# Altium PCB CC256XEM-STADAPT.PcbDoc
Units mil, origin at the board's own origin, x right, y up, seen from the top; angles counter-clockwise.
Board outline 2600 x 2900 mil, 4 copper layers (Top Layer, Layer 2, Layer 3, Bottom Layer), stack 62 mil thick; 64 components, 60 nets, 306 pads, 134 vias.
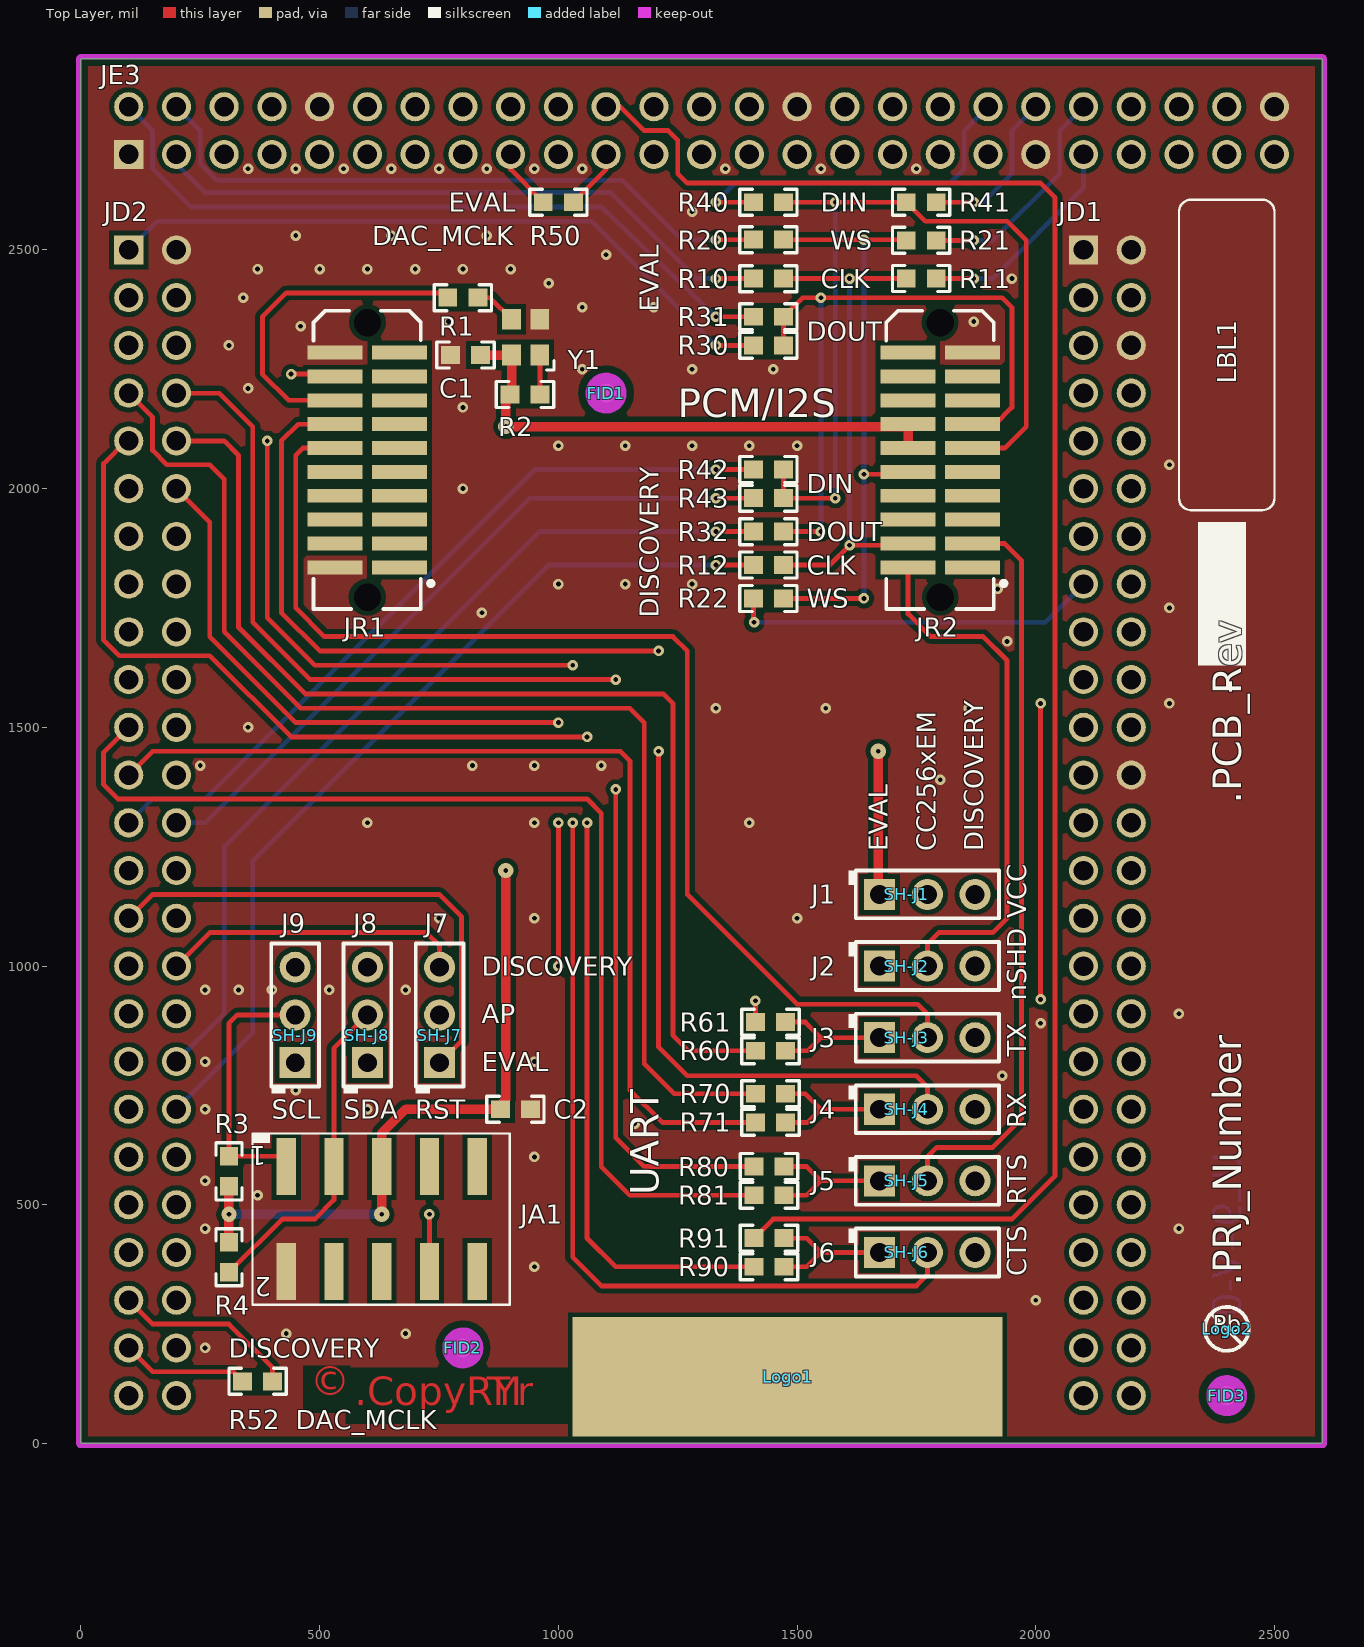
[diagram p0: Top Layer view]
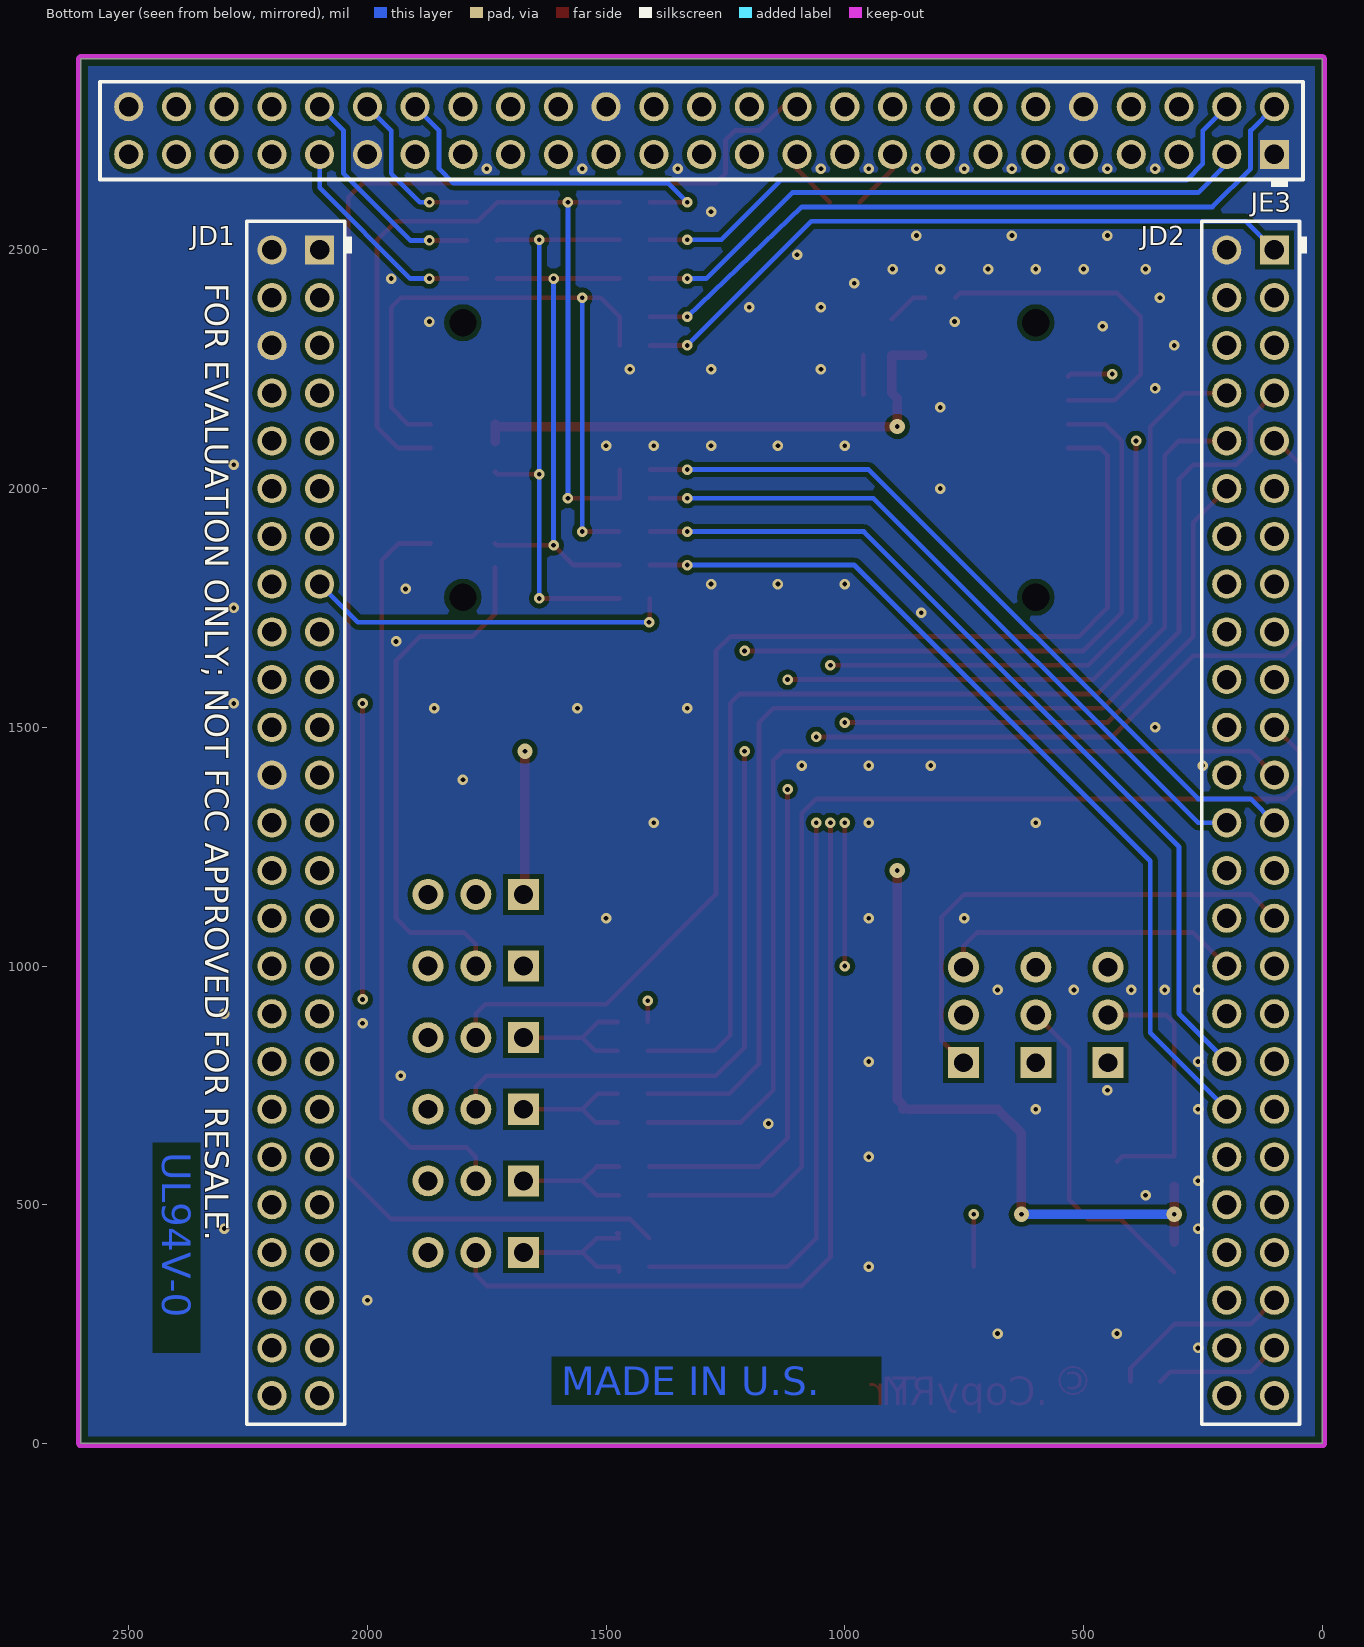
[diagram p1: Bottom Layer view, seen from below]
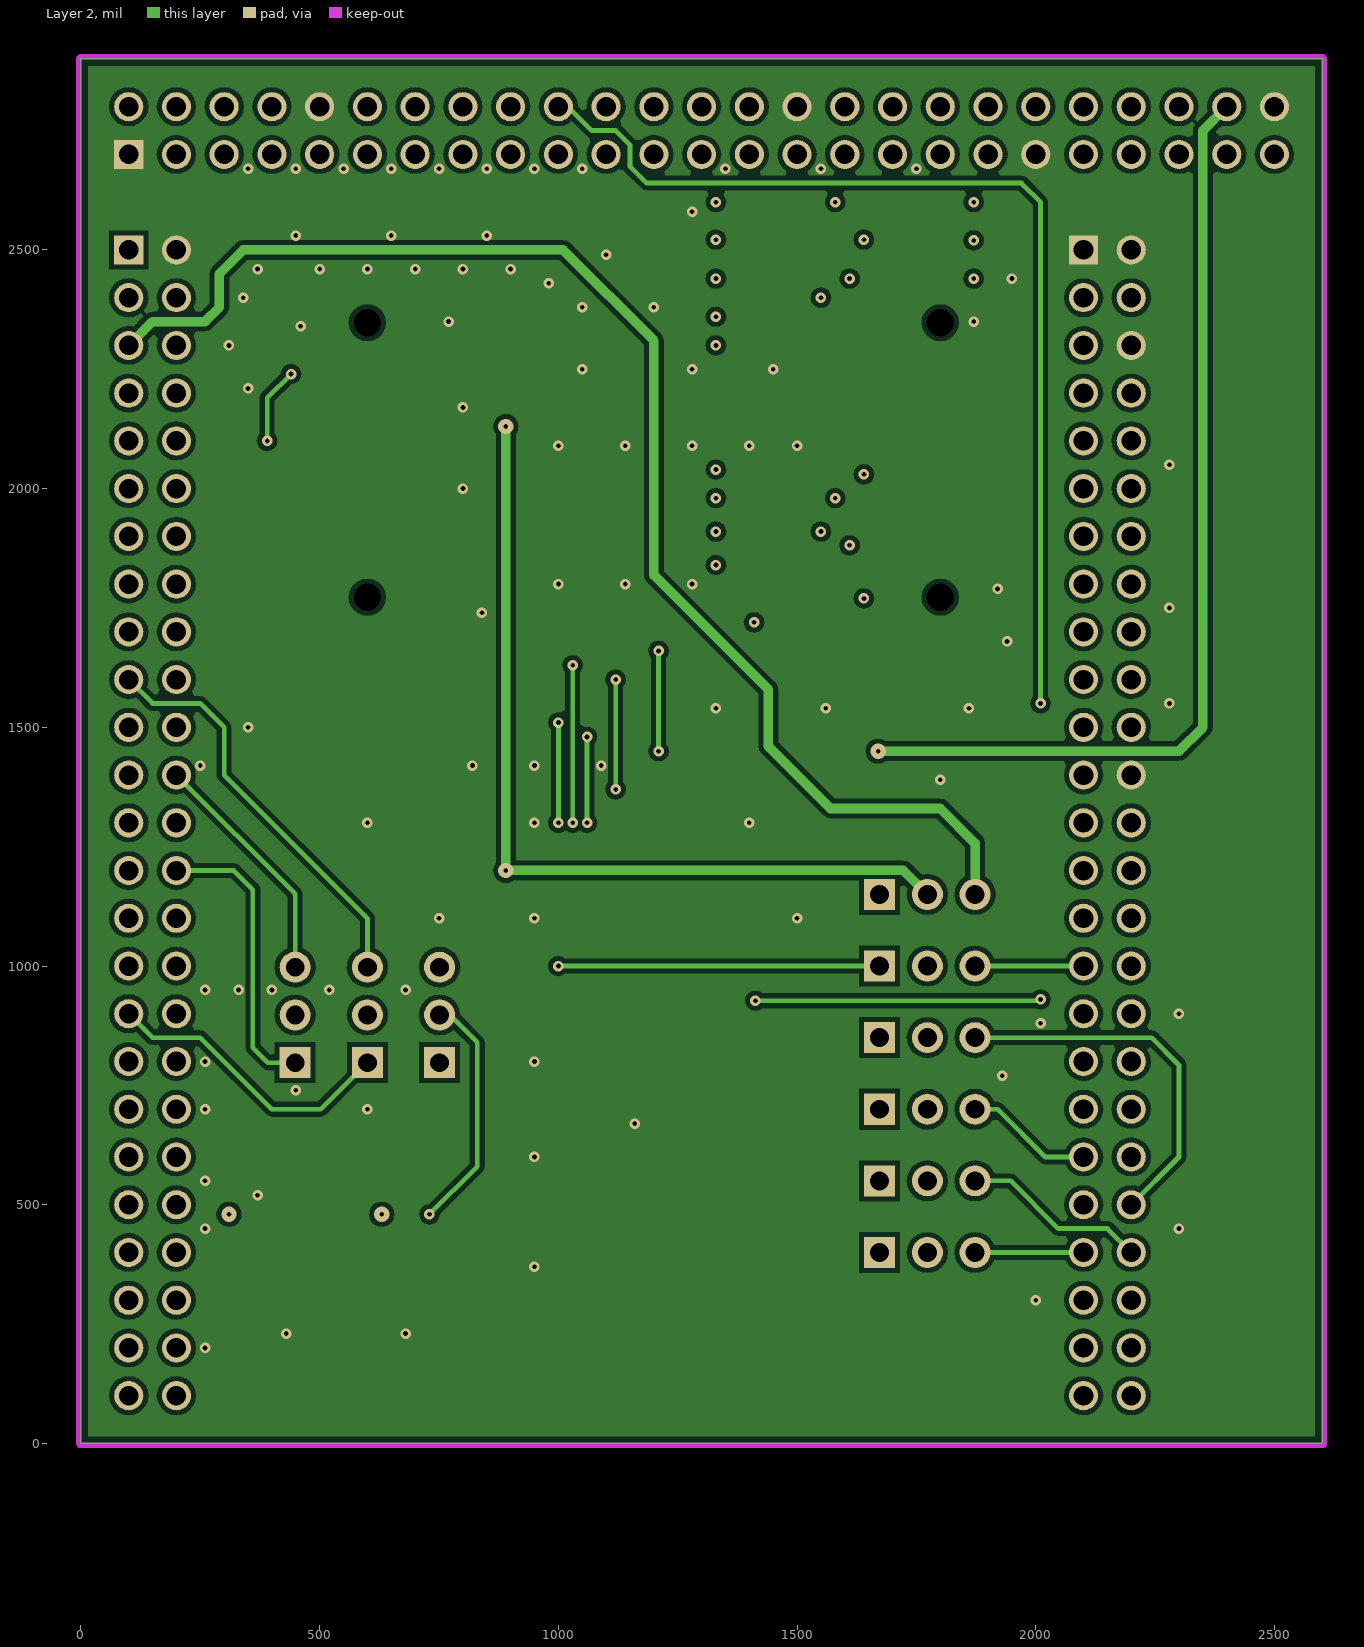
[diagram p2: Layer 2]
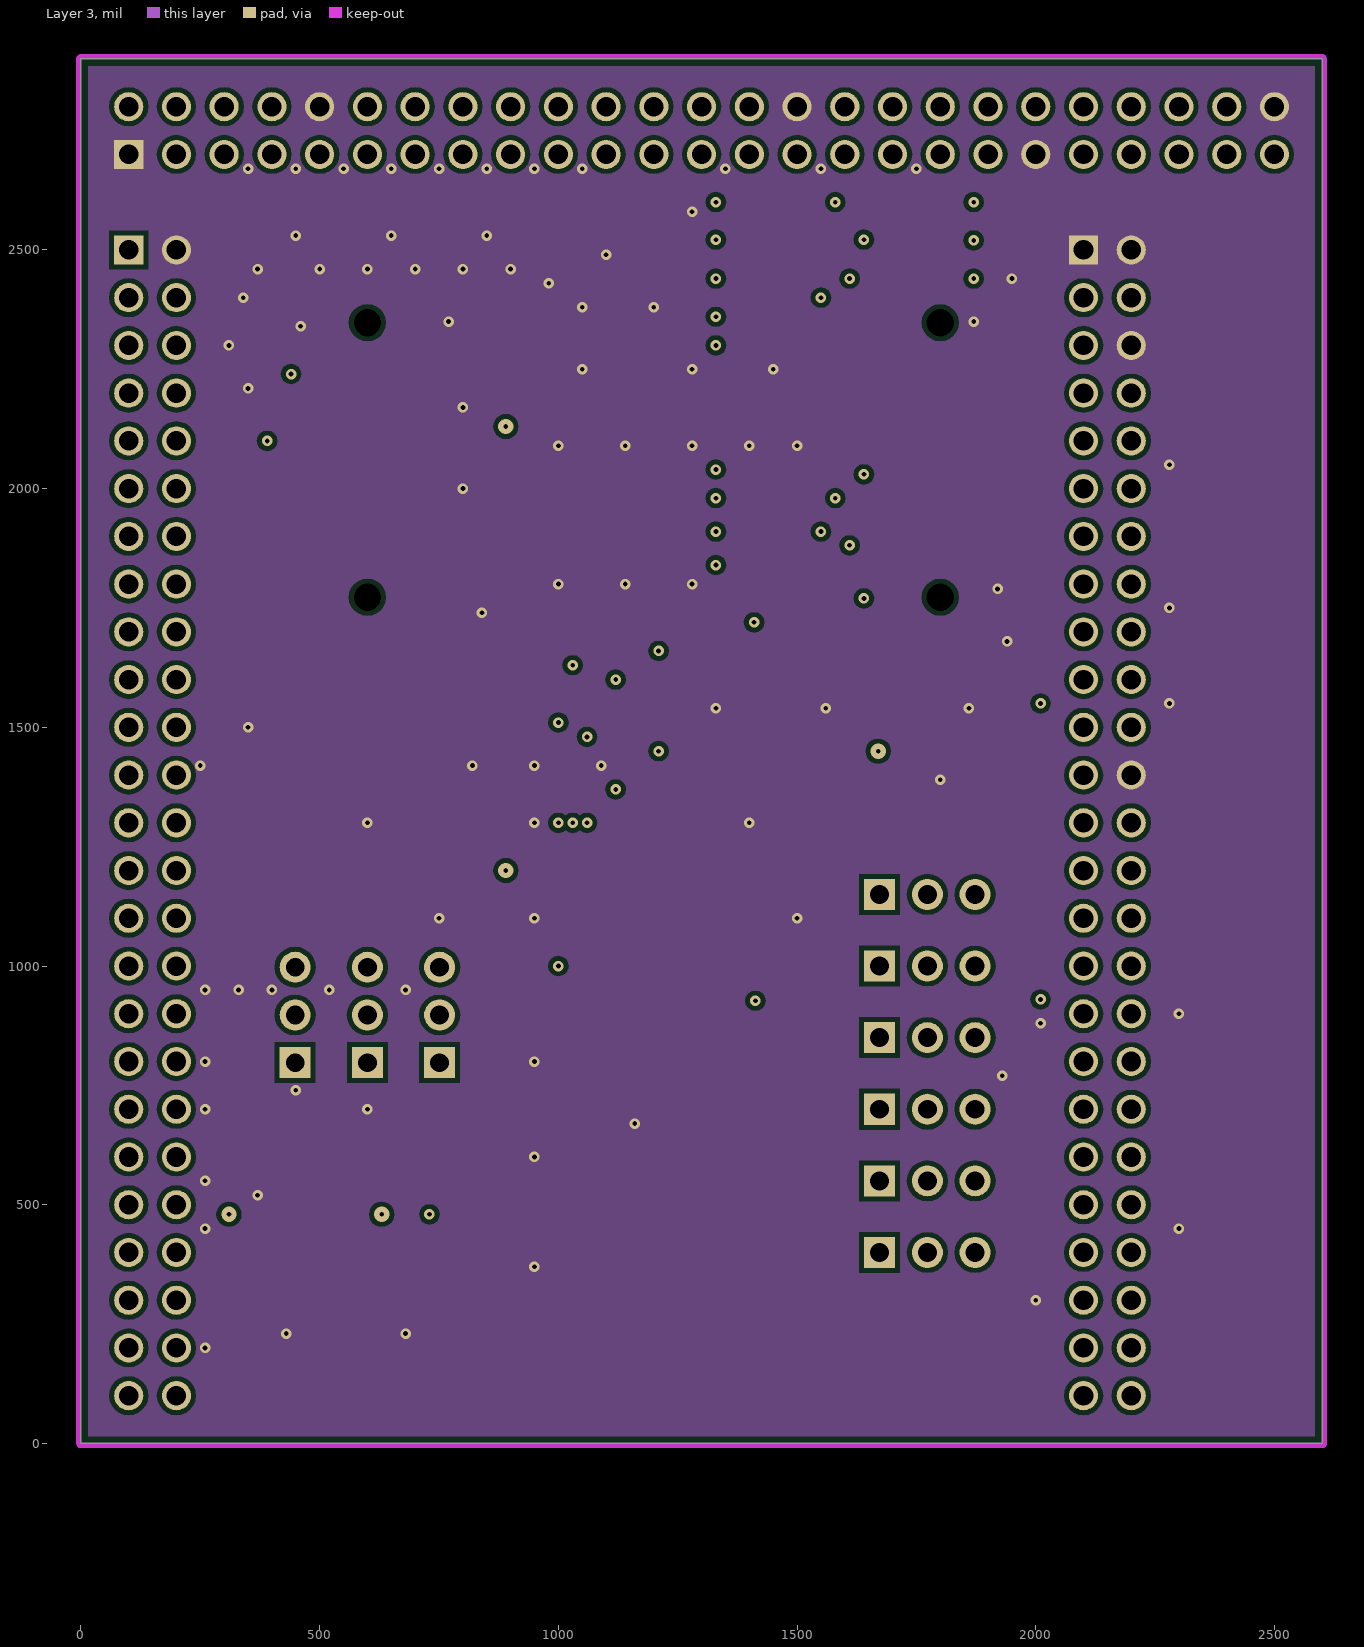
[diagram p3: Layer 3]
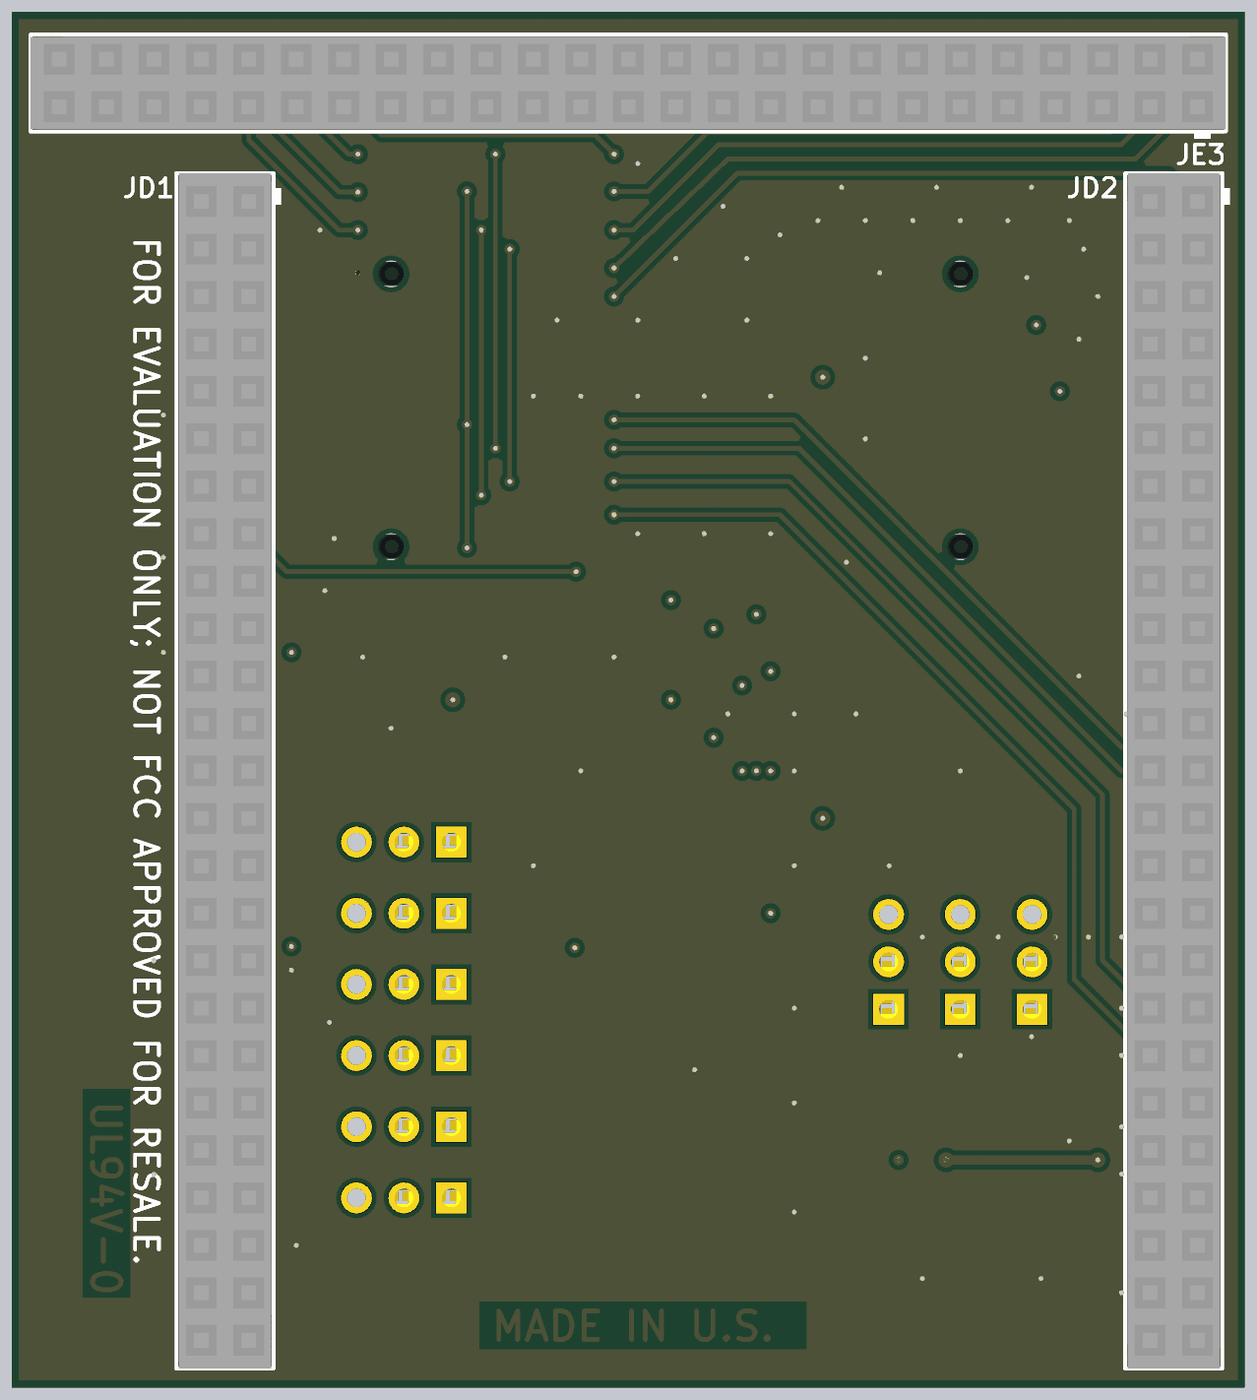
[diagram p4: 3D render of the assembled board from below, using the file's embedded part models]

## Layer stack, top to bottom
Top Solder: solder mask 0.4, Solder Resist, Dk 3.5
Top Layer: signal copper 1.4
Dielectric 1: core 10, FR-4, Dk 4.8
Layer 2: signal copper 1.4
Dielectric 2: prepreg 36.4, FR-4, Dk 4.8
Layer 3: signal copper 1.4
Dielectric 3: core 10, FR-4, Dk 4.8
Bottom Layer: signal copper 1.4
Bottom Solder: solder mask 0.4, Solder Resist, Dk 3.5

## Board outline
0,0 2600,0 2600,2900 0,2900

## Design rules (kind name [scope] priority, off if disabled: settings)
AcuteAngle [All] p1: minimum=4.50000000000000E+0001 checktracksonly=FALSE
AssemblyTestPointUsage [All] p1: valid=2
Clearance Clearance_Keepouts [((IsTrack Or IsArc) And Not InPoly) And IsFree and IsKeepOut vs ((IsTrack Or IsArc) And Not InPoly) And IsFree and IsKeepOut] p1: gap=0
Clearance Clearance_BoardEdge_MountingHoles [OnCopper and InComponentClass('Mounting Holes') vs IsKeepOut] p2: gap=40
Clearance Clearance_BoardEdge_Poly [OnCopper and InPoly vs IsKeepOut] p3: gap=15
Clearance Clearance_BoardEdge [OnCopper and Not InComponentClass('Logo') and not InComponentClass('FiducialMark') and not InRegion(1000,500,4000,800) and Not IsKeepout vs IsKeepOut] p4: gap=15
Clearance Clearance_Poly [InPolygon] p5: gap=10
Clearance [All] p6: gap=8
ComponentClearance ComponentClearance_MountingHoles_FiducialMarks [InComponentClass('Mounting Holes') vs InComponentClass('FiducialMark')] p1: gap=50 collisioncheckmode=3 verticalgap=10 showdistances=FALSE
ComponentClearance ComponentClearance_Shunt [InComponentClass('Header') vs InComponentClass('Shunt')] p2: gap=0 collisioncheckmode=3 verticalgap=0 showdistances=FALSE
ComponentClearance ComponentClearance_Logo [InComponentClass('Logo')] p3: gap=50 collisioncheckmode=3 verticalgap=10 showdistances=FALSE
ComponentClearance ComponentClearance_ScrewToNut [(HasFootprint('NY PMS 440 0025 PH')) vs (HasFootprint('Keystone_1902C'))] p4: gap=5 collisioncheckmode=3 verticalgap=10 showdistances=FALSE
ComponentClearance ComponentClearance_MountingHoles [InComponentClass('Mounting Holes')] p5: gap=250 collisioncheckmode=3 verticalgap=100000 showdistances=FALSE
ComponentClearance ComponentClearance_SmallPassives [HasFootprint('0201*') or HasFootprint('0402*') or HasFootprint('0508') or HasFootprint('0603*') or HasFootprint('0612') or HasFootprint('0805*') or HasFootprint('0815*') or HasFootprint('0830*') or HasFootprint('1206*') or HasFootprint('1210*') or HasFootprint('1808*') or HasFootprint('1812*') or HasFootprint('1825*') or HasFootprint('2010*') or HasFootprint('2220*') or HasFootprint('2225*') or HasFootprint('2512*') or HasFootprint('2728*') or HasFootprint('3518*') vs HasFootprint('0201*') or HasFootprint('0402*') or HasFootprint('0508') or HasFootprint('0603*') or HasFootprint('0612') or HasFootprint('0805*') or HasFootprint('0815*') or HasFootprint('0830*') or HasFootprint('1206*') or HasFootprint('1210*') or HasFootprint('1808*') or HasFootprint('1812*') or HasFootprint('1825*') or HasFootprint('2010*') or HasFootprint('2220*') or HasFootprint('2225*') or HasFootprint('2512*') or HasFootprint('2728*') or HasFootprint('3518*')] p6: gap=20 collisioncheckmode=3 verticalgap=10 showdistances=FALSE
ComponentClearance ComponentClearance_THtoSMT [IsThruComponent vs IsSMTComponent] p7: gap=40 collisioncheckmode=3 verticalgap=30 showdistances=FALSE
ComponentClearance ComponentClearance_THtoTH [IsThruComponent vs IsThruComponent] p8: gap=40 collisioncheckmode=3 verticalgap=30 showdistances=FALSE
ComponentClearance [All] p9: gap=40 collisioncheckmode=3 verticalgap=10 showdistances=FALSE
DiffPairsRouting [All] p1: maxlimit=100 minlimit=10 mostfreqgap=10 toplayer_minwidth=15 toplayer_maxwidth=15 toplayer_prefwidth=15 midlayer1_minwidth=15 midlayer1_maxwidth=15 midlayer1_prefwidth=15 midlayer2_minwidth=15 midlayer2_maxwidth=15 midlayer2_prefwidth=15 bottomlayer_minwidth=15 bottomlayer_maxwidth=15 bottomlayer_prefwidth=15 maxuncoupledlength=1000
FabricationTestPointUsage TestPointUsage [All] p1: valid=2 allowmultiple=FALSE
FabricationTestpoint Testpoint [All] p1: side=3 testpointundercomponent=TRUE minsize=40 maxsize=100 preferedsize=60 minholesize=0 maxholesize=40 preferedholesize=32 testpointgrid=1 allowsidetop=TRUE allowsidebottom=TRUE usegrid=TRUE gridtolerance=0.01
FanoutControl Fanout_LCC [IsLCC] p1: bgadir=Out bgaviamode=Centered fanoutstyle=Auto fanoutdirection=Alternating viagrid=1 // Fanout_LCC (Default Rule)
FanoutControl Fanout_BGA [IsBGA] p2: bgadir=Out bgaviamode=Centered fanoutstyle=Auto fanoutdirection=Alternating viagrid=1 // Fanout_BGA (Default Rule)
FanoutControl Fanout_Default [All] p4: bgadir=Out bgaviamode=Centered fanoutstyle=Auto fanoutdirection=Alternating viagrid=1 // Fanout_Default (Default Rule)
FanoutControl Fanout_Small [(CompPinCount < 5)] p5: bgadir=Out bgaviamode=Centered fanoutstyle=Auto fanoutdirection=OutThenIn viagrid=1 // Fanout_Small (Default Rule)
HoleSize [All] p1: absolutevalues=TRUE maxlimit=251 minlimit=10 maxpercent=80.000 minpercent=20.000
MinimumAnnularRing MinimumAnnularRing_ThermalPadVias [IsVia and InAnyComponent] p1: minimumring=6
MinimumAnnularRing [All] p2: minimumring=5
MinimumSolderMaskSliver MinimumSolderMaskSliver_Logo [InComponentClass('Logo') vs InComponentClass('Logo')] p1: minsoldermaskwidth=0.7
MinimumSolderMaskSliver [All] p2: minsoldermaskwidth=3.94
PlaneConnect [All] p1: planeconnectstyle=Relief reliefexpansion=10 reliefentries=4 reliefconductorwidth=10 reliefairgap=10
PolygonConnect [All] p1: connectstyle=Direct reliefconductorwidth=10 reliefentries=4 polygonreliefangle="90 Angle" airgapwidth=10
RoutingVias ThermalPadVias [IsVia and InAnyComponent] p1: holewidth=10 width=32 viastyle="Through Hole" minholewidth=10 minwidth=24 maxholewidth=15 maxwidth=29
RoutingVias [All] p2: holewidth=10 width=22 viastyle="Through Hole" minholewidth=10 minwidth=22 maxholewidth=40 maxwidth=65
SilkToBoardRegionClearance [Not ((IsComment or IsDesignator) And (Hide <> 'False')) and not InRegion(1000,500,4000,800)] p1:
SilkToSilkClearance SilkToSilkClearance_PCB-Rev [(OnLayer('Top Overlay') AND (IsFill OR IsText)) vs (OnLayer('Top Overlay') AND (IsFill OR IsText))] p1: silktosilkclearance=0
SilkToSilkClearance SilkToSilkClearance_Pb-FreeLogo [(HasFootprint('Pb-Free_Overlay_Medium') OR HasFootprint('Pb-Free_Overlay_Small')) vs (HasFootprint('Pb-Free_Overlay_Medium') OR HasFootprint('Pb-Free_Overlay_Small'))] p2: silktosilkclearance=0
SilkToSilkClearance [All] p3: silktosilkclearance=4
SilkToSolderMaskClearance "Silk to Solder Mask Opening" [All] p1: minsilkscreentomaskgap=1 clearancetoexposedcopper=FALSE
SolderMaskExpansion [All] p1: expansion=1.97
UnpouredPolygon [All] p1: allowunpoured=FALSE
Width Width_PWR_GND [(InNet('GND') OR InNet('CC_VCC') OR InNet('DISCOVERY_VCC') OR InNet('EVAL_VCC'))] p1: maxlimit=100 minlimit=15 preferedwidth=20 checkconnectedcopper=TRUE
Width [All] p2: maxlimit=100 minlimit=6 preferedwidth=10 checkconnectedcopper=TRUE
14 further rules are at their usual default settings.

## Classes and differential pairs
component class Label: LBL1
component class AssemblyNote: ZZ1 ZZ2 ZZ3 ZZ4
component class FiducialMark: FID1 FID2 FID3
component class CC256XEM-STADAPT_Hardware: FID1 FID2 FID3 LBL1 Logo1 Logo2 SH-J1 SH-J2 SH-J3 SH-J4 SH-J5 SH-J6 SH-J7 SH-J8 SH-J9 ZZ1 ZZ2 ZZ3 ZZ4
component class Logo: Logo1
component class Header: J1 J2 J3 J4 J5 J6 J7 J8 J9
component class CC256XEM-STADAPT_Schematics: C1 C2 J1 J2 J3 J4 J5 J6 J7 J8 J9 JA1 JD1 JD2 JE3 JR1 JR2 R1 R2 R3 R4 R10 R11 R12 R20 R21 R22 R30 R31 R32 R40 R41 R42 R43 R50 R52 R60 R61 R70 R71 R80 R81 R90 R91 Y1
component class Shunt: SH-J1 SH-J2 SH-J3 SH-J4 SH-J5 SH-J6 SH-J7 SH-J8 SH-J9

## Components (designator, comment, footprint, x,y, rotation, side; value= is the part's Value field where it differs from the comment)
C1 "GRM188R71C104KA01D" 0603 805.55,2280 r0 top
C2 "GRM188R71C104KA01D" 0603 910,700 r180 top
FID1 "Fiducial" Fiducial10-20 1100,2200 r0 top
FID2 "Fiducial" Fiducial10-20 800,200 r0 top
FID3 "Fiducial" Fiducial10-20 2400,100 r0 top
J1 "VCC" TE_5-146278-3 1772.97,1150 r0 top
J2 "nSHD" TE_5-146278-3 1772.97,1000 r0 top
J3 "TX" TE_5-146278-3 1772.97,850 r0 top
J4 "RX" TE_5-146278-3 1772.97,700 r0 top
J5 "RTS" TE_5-146278-3 1772.97,550 r0 top
J6 "CTS" TE_5-146278-3 1772.97,400 r0 top
J7 "RST" TE_5-146278-3 751.25,897.5 r90 top
J8 "SDA" TE_5-146278-3 600,897.5 r90 top
J9 "SCL" TE_5-146278-3 448.75,897.5 r90 top
JA1 "SSW-105-22-F-D-VS-K" CONN_SSW-105-22-F-D-VS-K 630,470 r180 top
JD1 "JD1" Samtec_SSW-125-01-x-D 2150,1300 r270 bottom locked
JD2 "JD2" Samtec_SSW-125-01-x-D 150,1300 r270 bottom locked
JE3 "JE3" Samtec_SSW-125-01-x-D 1300,2750 r0 bottom locked
JR1 "TFM-110-02-L-D-A" Samtec_TFM-110-02-L-D-A 600,2060 r90 top
JR2 "TFM-110-02-L-D-A" Samtec_TFM-110-02-L-D-A 1800,2060 r90 top
LBL1 "Size: 0.65\" x 0.20 \"" Label_650x200 2400,2280 r90 top
Logo1 "Texas Instruments" TI_Stacked_SolderMask_Small 1480,140 r0 top
Logo2 "Pb-Free Symbol" Pb-Free_Overlay_Small 2400,240 r0 top
R1 "RC0603JR-070RL" 0603 800,2400 r180 top
R2 "RC0603FR-071KL" 0603 930,2197.24 r180 top
R3 "RC0603JR-072K2L" 0603 310,570 r90 top
R4 "RC0603JR-072K2L" 0603 310,390 r270 top
R10 "RC0603JR-070RL" 0603 1440,2440 r180 top
R11 "RC0603JR-070RL" 0603 1760,2440 r0 top
R12 "RC0603JR-070RL" 0603 1440,1840 r180 top
R20 "RC0603JR-070RL" 0603 1440,2521.46 r180 top
R21 "RC0603JR-070RL" 0603 1760,2520 r0 top
R22 "RC0603JR-070RL" 0603 1440,1770 r180 top
R30 "RC0603JR-070RL" 0603 1440,2300 r180 top
R31 "RC0603JR-070RL" 0603 1440,2360 r180 top
R32 "RC0603JR-070RL" 0603 1440,1910 r180 top
R40 "RC0603JR-070RL" 0603 1440,2600 r180 top
R41 "RC0603JR-070RL" 0603 1760,2600 r0 top
R42 "RC0603JR-070RL" 0603 1440,2040 r180 top
R43 "RC0603JR-070RL" 0603 1440,1980 r180 top
R50 "RC0603JR-070RL" 0603 1000,2600 r0 top
R52 "RC0603JR-070RL" 0603 370,130 r180 top
R60 "RC0603JR-070RL" 0603 1444.27,822.5 r180 top
R61 "RC0603JR-070RL" 0603 1444.27,882.5 r180 top
R70 "RC0603JR-070RL" 0603 1444.27,732.5 r180 top
R71 "RC0603JR-070RL" 0603 1444.27,672.5 r180 top
R80 "RC0603JR-070RL" 0603 1441.3,580 r180 top
R81 "RC0603JR-070RL" 0603 1441.3,520 r180 top
R90 "RC0603JR-070RL" 0603 1441.3,370 r180 top
R91 "RC0603JR-070RL" 0603 1441.3,430 r180 top
SH-J1 "Shunt for J1-VCC" SNT-100-BK-G 1730.12,1150 r180 top
SH-J2 "Shunt for J2-nSHUTD" SNT-100-BK-G 1730.12,1000 r180 top
SH-J3 "Shunt for J3-UART_TX" SNT-100-BK-G 1730.12,850 r180 top
SH-J4 "Shunt for J4-UART_RX" SNT-100-BK-G 1730.12,700 r180 top
SH-J5 "Shunt for J5-UART_RTS" SNT-100-BK-G 1730.12,550 r180 top
SH-J6 "Shunt for J6-UART_CTS" SNT-100-BK-G 1730.12,400 r180 top
SH-J7 "Shunt for J7-AP_RST" SNT-100-BK-G 751.25,854.65 r90 top
SH-J8 "Shunt for J8-AP_SDA" SNT-100-BK-G 600,854.65 r90 top
SH-J9 "Shunt for J9-AP_SCL" SNT-100-BK-G 448.75,854.65 r90 top
Y1 "501BCAM032768DAG" Si50x_2x2-5 931.61,2317.24 r180 top
ZZ1 "This Assembly Note is for PCB labels only" AssemblyNoteLabel 175,3943 r0 top
ZZ2 "These assemblies are ESD sensitive, ESD precautions shall be observed." AssemblyNote 175,3834.11 r0 top
ZZ3 "These assemblies must be clean and free from flux and all contaminants. Use of no clean flux is not acceptable." AssemblyNote 175,3745.56 r0 top
ZZ4 "These assemblies must comply with workmanship standards IPC-A-610 Class 2, unless otherwise specified." AssemblyNote 175,3657 r0 top

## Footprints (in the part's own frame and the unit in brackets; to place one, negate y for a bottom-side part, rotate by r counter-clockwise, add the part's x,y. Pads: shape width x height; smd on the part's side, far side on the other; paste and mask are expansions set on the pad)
0603 [mm] "0603 from SM-752 data"
  rect 1x0.95 smd: 1(-0.8,0) 2(0.8,0)
  silkscreen extent -1.52,-0.69 1.52,0.69, body extent -0.87,-0.47 0.87,0.47, height 0.85
AssemblyNote [mil] "Assembly Note"
AssemblyNoteLabel [mil] "Assembly Note for PCB Labels"
CONN_SSW-105-22-F-D-VS-K [mil]
  rect 40x120 smd: 1(200,-110) 2(200,110) 3(100,-110) 4(100,110) 5(0,-110) 6(0,110) 7(-100,-110) 8(-100,110) 9(-200,-110) 10(-200,110)
  silkscreen extent -268,-179 271,179, body extent -260,-155 250,155, height 435
Fiducial10-20 [mm]
  round 1 smd mask+0.5: 1(0,0)
  Top Layer keep-out circle w1.178: c0,0 r0.5
Label_650x200 [mil] "Thermal Transfer Label"
  silkscreen extent -325,-100 325,100, body extent -326,-101 326,101, height 1
Pb-Free_Overlay_Small [mil]
  silkscreen extent -46,-46 46,46
Samtec_SSW-125-01-x-D [mm] "Receptacle, 2.54mm, 2x25, TH"
  rect 1.55x1.55 hole 1.04: 1(-30.48,1.27)
  round 1.55 hole 1.04: 2(-30.48,-1.27) 3(-27.94,1.27) 4(-27.94,-1.27) 5(-25.4,1.27) 6(-25.4,-1.27) 7(-22.86,1.27) 8(-22.86,-1.27) 9(-20.32,1.27) 10(-20.32,-1.27) 11(-17.78,1.27) 12(-17.78,-1.27) 13(-15.24,1.27) 14(-15.24,-1.27) 15(-12.7,1.27) 16(-12.7,-1.27) 17(-10.16,1.27) 18(-10.16,-1.27) 19(-7.62,1.27) 20(-7.62,-1.27) 21(-5.08,1.27) 22(-5.08,-1.27) 23(-2.54,1.27) 24(-2.54,-1.27) 25(0,1.27) 26(0,-1.27) 27(2.54,1.27) 28(2.54,-1.27) 29(5.08,1.27) 30(5.08,-1.27) 31(7.62,1.27) 32(7.62,-1.27) 33(10.16,1.27) 34(10.16,-1.27) 35(12.7,1.27) 36(12.7,-1.27) 37(15.24,1.27) 38(15.24,-1.27) 39(17.78,1.27) 40(17.78,-1.27) 41(20.32,1.27) 42(20.32,-1.27) 43(22.86,1.27) 44(22.86,-1.27) 45(25.4,1.27) 46(25.4,-1.27) 47(27.94,1.27) 48(27.94,-1.27) 49(30.48,1.27) 50(30.48,-1.27)
  silkscreen extent -32,-2.6 32,3, body extent -32,-2.48 32,2.48, height 8.41
Samtec_TFM-110-02-L-D-A [mm] "Samtec"
  rect 0.74x2.92 smd paste+0: 1(-5.715,-1.715) 2(-5.715,1.715) 3(-4.445,-1.715) 4(-4.445,1.715) 5(-3.175,-1.715) 6(-3.175,1.715) 7(-1.905,-1.715) 8(-1.905,1.715) 9(-0.635,-1.715) 10(-0.635,1.715) 11(0.635,-1.715) 12(0.635,1.715) 13(1.905,-1.715) 14(1.905,1.715) 15(3.175,-1.715) 16(3.175,1.715) 17(4.445,-1.715) 18(4.445,1.715) 19(5.715,-1.715) 20(5.715,1.715)
  round 0.508 hole 1.45 unplated paste+0: MH1(-7.305,0) MH2(7.305,0)
  silkscreen extent -7.93,-3.49 7.95,2.87, body extent -7.93,-2.95 7.94,3.02, height 5.74
Si50x_2x2-5 [mm] "Silicon Labs"
  rect 1x1.1 smd: 1(-0.75,0.95) 2(-0.75,-0.95) 3(0.75,-0.95) 4(0.75,0.95)
  silkscreen extent -1.5,1.25 -1.1,1.75, body extent -1.07,-1.32 1.07,1.32, height 0.91
SNT-100-BK-G [mil] "Samtec STEP model"
  round 1 on Mech3: 0(0,0)
  body extent -100,-50 100,50, height 344
TE_5-146278-3 [mm] "TE CONNECTIVITY"
  rect 1.65x1.65 hole 1: 1(-2.54,0)
  round 1.65 hole 1: 2(0,0) 3(2.54,0)
  silkscreen extent -4.19,-1.27 3.81,1.27, body extent -3.68,-1.17 3.68,1.17, height 8.13
TI_Stacked_SolderMask_Small [mil]
  rect 900x250 smd paste-125 mask-125: 0(0,0)

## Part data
C1 C2: "CAP, CERM, 0.1 µF, 16 V, +/- 10%, X7R, 0603"
FID1 FID2 FID3: "Fiducial mark.  There is nothing to buy or mount."
J1 J2 J3 J4 J5 J6 J7 J8 J9: library part 5-146278-3, "Header, 100mil, 3x1, Tin, TH"
JA1: "Connector, Header, 10-Pos (5x2), Receptacle, 100x100-mil Pitch"
JD1 JD2 JE3: library part SSW-125-01-T-D, "Receptacle, 2.54mm, 2x25, TH"
JR1 JR2: "Straight Low Profile Header, 10x2 Position,1.27 mm Pitch, SMT"
LBL1: library part THT-14-423-10, "Thermal Transfer Printable Labels, 0.650\" W x 0.200\" H - 10,000 per roll"
Logo1: library part TI_Logo, "Texas Instrument Corporate Signature"
Logo2: library part Pb-Free
R1 R10 R11 R12 R20 R21 R22 R30 R31 R32 R40 R41 R42 R43 R50 R52 R60 R61 R70 R71 R80 R81 R90 R91: "RES, 0, 5%, 0.1 W, 0603"
R2: "RES, 1.00 k, 1%, 0.1 W, 0603"
R3 R4: "RES, 2.2 k, 5%, 0.1 W, 0603"
SH-J1 SH-J2 SH-J3 SH-J4 SH-J5 SH-J6 SH-J7 SH-J8 SH-J9: library part 969102-0000-DA, "Shunt, 100mil, Gold plated, Black"
Y1: "OSC, 32.768kHz, 3.3V, SMD"
ZZ1: library part AssemblyNoteLabel
ZZ2 ZZ3 ZZ4: library part AssemblyNote

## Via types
v1: diameter 22, hole 10, Top Layer to Bottom Layer, tented both sides, 129 vias
v2: diameter 32, hole 10, Top Layer to Bottom Layer, tented both sides, 5 vias

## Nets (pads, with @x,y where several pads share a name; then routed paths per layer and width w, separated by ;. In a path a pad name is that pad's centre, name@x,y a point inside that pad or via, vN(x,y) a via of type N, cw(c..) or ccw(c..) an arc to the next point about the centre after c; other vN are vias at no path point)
AP_RST: J7.2 JA1.8 | length 614
  Top Layer w10: JA1.8@730,370 v1(730,480)
  Layer 2 w10: v1(730,480) 830,580 830,840 772.5,897.5 J7.2
AP_SCL: J9.2 JA1.1 R3.2 | length 549.3
  Top Layer w10: JA1.1@430,590 418.5,601.5 R3.2 310,880 327.5,897.5 J9.2
AP_SDA: J8.2 JA1.3 R4.2 | length 699.2
  Top Layer w10: R4.2 421.5,470 490,470 530,510 530,590 530,827.49 J8.2
AP_VCC: C1.2 C2.2 J1.2 JA1.5 JR2.12 JR2.14 R2.2 R3.1 R4.1 Y1.4 | length 4274.5
  Top Layer w20: R4.1 v2(310,480) R3.1 ; v2(630,480) 630,590 630,650 680,700 C2.2@868.5,700 ; C1.2 837.21,2279.84 Y1.4 902.09,2200.83 R2.2 R2.2@890,2188.74 ; C2.2 878.5,708.86 890,720.35 v2(890,1200) ; v2(890,2130) JR2.14@1722.48,2130 ; v2@890,2140 R2.2@890,2178.74 ; JR2.12@1732.48,2098 JR2.14
  Layer 2 w20: v2(890,2130) v2(890,1200) 890.48,1200.48 1722.49,1200.48 J1.2
  Bottom Layer w20: v2(310,480) v2(630,480)
CC_NSHUTD: J2.2 JR2.2 | length 1120.8
  Top Layer w10: JR2.2 1732.48,1737.52 1780,1690 1890,1690 1940,1640 1940,1100 1910,1070 1796.99,1070 1772.97,1045.98 J2.2
CC_PCM_CLK: JR2.4 R10.1 R11.1 R12.1 | length 1135.3
  Top Layer w10: R12.1 1568.7,1840 v1(1610,1881.3) 1728.78,1881.3 JR2.4 ; R10.1 v1(1610,2440) R11.1
  Bottom Layer w10: v1(1610,1881.3) 1610,1965 ; 1610,1925 v1(1610,2440)
CC_PCM_DIN: JR2.11 R40.1 R41.1 R42.1 R43.1 | length 1851.3
  Top Layer w10: R42.1 R43.1 v1(1580,1980) ; R40.1 v1(1580,2600) R41.1 1768.5,2560 1940,2560 1980,2520 1980,2130 1935,2085 JR2.11
  Bottom Layer w10: v1(1580,1980) v1(1580,2600)
CC_PCM_DOUT: JR2.13 R30.1 R31.1 R32.1 | length 1437.4
  Top Layer w10: R30.1 R31.1 1511.5,2400 v1(1550,2400) 1930,2400 1950,2380 1950,2170 1915,2135 JR2.13 ; R32.1@1472.95,1910 v1(1550,1910)
  Bottom Layer w10: v1(1550,1910) v1(1550,2400)
CC_PCM_FSYNC: JR2.10 R20.1 R21.1 R22.1 | length 1272.1
  Top Layer w10: R22.1 v1(1640,1770) ; R20.1 v1(1640,2521.46) 1727.05,2521.46 R21.1 ; v1(1640,2030) 1727.48,2030 JR2.10
  Bottom Layer w10: v1(1640,1770) v1(1640,2030) 1640,2075 v1(1640,2521.46)
CC_SLOW_CLK: JR1.16 R1.2 | length 708.6
  Top Layer w10: JR1.16 435,2185 380,2240 380,2360 430,2410 758.5,2410 R1.2
CC_UART_CTS: J6.2 JR1.18 | length 3371.1
  Top Layer w10: v1(390,2100) 390,1730 490,1630 v1(1030,1630) ; v1(440,2240) 527.48,2240 JR1.18 ; v1(1030,1300) 1030,390 1090,330 1750,330 1772.97,352.97 J6.2
  Layer 2 w10: v1(390,2100) 390,2190 v1(440,2240) ; v1(1030,1300) v1(1030,1630)
CC_UART_RTS: J5.2 JR2.3 | length 1567.1
  Top Layer w10: J5.2 1772.97,600 1792.97,620 1910,620 1970,680 1970,1850 1935,1885 JR2.3
CC_UART_RX: J4.2 JR1.14 | length 2784.5
  Top Layer w10: JR1.14 455,2135 420,2100 420,1740 500,1660 v1(1210,1660) ; v1(1210,1450) 1210,830 1270,770 1750,770 1772.97,747.03 J4.2
  Layer 2 w10: v1(1210,1450) v1(1210,1660)
CC_UART_TX: J3.2 JR1.12 | length 2432.5
  Top Layer w10: JR1.12 465,2085 450,2070 450,1750 510,1690 1240,1690 1270,1660 1270,1150 1500,920 1752.97,920 1772.97,900 J3.2
DISCOVERY_CC_NSHUTD: J2.3 JD1.31 | length 227
  Layer 2 w10: J2.3 JD1.31
DISCOVERY_CP_RST: J7.3 JD2.32 | length 636.6
  Top Layer w10: JD2.32 270,1070 723.73,1070 751.25,1042.48 J7.3
DISCOVERY_DAC_DIN: JD2.36 R32.2 | length 1873.3
  Top Layer w10: v1(1330,1910) R32.2
  Bottom Layer w10: JD2.36 300,900 300,1250 960,1910 v1(1330,1910)
DISCOVERY_DAC_MCLK: JD2.47 R52.2 | length 267.5
  Top Layer w10: JD2.47 150,150 318.5,150 R52.2
DISCOVERY_I2C1_SCL: J9.3 JD2.24 | length 505.5
  Layer 2 w10: JD2.24 448.75,1151.25 J9.3
DISCOVERY_I2C1_SDA: J8.3 JD2.19 | length 868.2
  Layer 2 w10: JD2.19 150,1550 250,1550 300,1500 300,1400 600,1100 J8.3
DISCOVERY_I2S3_CK: JD2.38 R12.2 | length 1891.6
  Top Layer w10: v1(1330,1840) R12.2
  Bottom Layer w10: JD2.38 360,860 360,1220 980,1840 v1(1330,1840)
DISCOVERY_I2S3_SD: JD2.25 R42.2 | length 1615
  Top Layer w10: v1(1330,2040) R42.2
  Bottom Layer w10: JD2.25 150,1350 260,1350 950,2040 v1(1330,2040)
DISCOVERY_I2S3_WS: JD1.15 R22.2 | length 773.8
  Top Layer w10: R22.2 1408.5,1721.5 v1(1410,1720)
  Bottom Layer w10: v1(1410,1720) 2020,1720 JD1.15
DISCOVERY_I2S3EXT_SD: JD2.26 R43.2 | length 1490.2
  Top Layer w10: v1(1330,1980) R43.2
  Bottom Layer w10: JD2.26 260,1300 940,1980 v1(1330,1980)
DISCOVERY_MCO: JD2.45 R52.1 | length 388.6
  Top Layer w10: JD2.45 150,250 310,250 401.5,158.5 R52.1
DISCOVERY_USART3_CTS: J5.3 JD1.44 | length 389.2
  Layer 2 w10: J5.3 1947.5,550 2047.5,450 2150,450 JD1.44
DISCOVERY_USART3_RTS: J6.3 JD1.43 | length 227
  Layer 2 w10: J6.3 JD1.43
DISCOVERY_USART3_RX: J3.3 JD1.42 | length 784.8
  Layer 2 w10: J3.3 2242.5,850 2300,792.5 2300,600 JD1.42
DISCOVERY_USART3_TX: J4.3 JD1.39 | length 268.5
  Layer 2 w10: J4.3 1920,700 2020,600 JD1.39
DISCOVERY_VCC: J1.3 JD2.5 | length 2876.6
  Layer 2 w20: JD2.5 150,2350 260,2350 290,2380 290,2450 340,2500 1010,2500 1200,2310 1200,1818.99 1438.99,1580 1440,1580 1440,1460 1570,1330 1800,1330 1872.97,1257.03 J1.3
EVAL_CC_NSHUTD: J2.1 JD2.12 | length 2326.5
  Top Layer w10: JD2.12 270,1930 270,1690 450,1510 v1(1000,1510) ; v1(1000,1000) v1(1000,1300)
  Layer 2 w10: v1(1000,1000) J2.1 ; v1(1000,1300) 1000,1450 v1(1000,1510)
EVAL_CP_RST: J7.1 JD2.29 | length 1061.8
  Top Layer w10: JD2.29 150,1150 750,1150 797.25,1102.75 797.25,843.5 J7.1
EVAL_DAC_DIN: JD2.1 R30.2 | length 1441.1
  Top Layer w10: v1(1330,2300) R30.2
  Bottom Layer w10: JD2.1 160,2560 1070,2560 v1(1330,2300)
EVAL_DAC_MCLK: JE3.21 R50.2 | length 128.4
  Top Layer w10: R50.2 1100,2668.5 JE3.21
EVAL_I2C1_SCL: J9.1 JD2.28 | length 613.3
  Layer 2 w10: JD2.28 320,1200 360,1160 360,828.75 391.26,797.5 J9.1
  Bottom Layer w10: JD2.28@200,1196.25 JD2.28
EVAL_I2C1_SDA: J8.1 JD2.33 | length 623.2
  Layer 2 w10: JD2.33 150,850 250,850 400,700 502.51,700 J8.1
EVAL_I2S2_CK_PB13: JE3.41 R11.2 | length 457.2
  Top Layer w10: R11.2 v1(1870,2440)
  Bottom Layer w10: v1(1870,2440) 1910,2440 2100,2630 JE3.41
EVAL_I2S2_CK_PI1: JE3.3 R10.2 | length 1327.9
  Top Layer w10: v1(1330,2440) R10.2
  Bottom Layer w10: JE3.3 200,2680 260,2620 1110,2620 1290,2440 v1(1330,2440)
EVAL_I2S2_SD: JE3.38 R40.2 | length 778.2
  Top Layer w10: v1(1330,2600) R40.2
  Bottom Layer w10: v1(1330,2600) 1370,2640 1820,2640 1850,2670 1850,2750 JE3.38
EVAL_I2S2_WS_PB12: JE3.42 R21.2 | length 477.2
  Top Layer w10: R21.2 v1(1870,2520)
  Bottom Layer w10: v1(1870,2520) 1910,2520 2050,2660 2050,2750 JE3.42
EVAL_I2S2_WS_PI0: JE3.4 R20.2 | length 1364.9
  Top Layer w10: v1(1330,2521.46) R20.2
  Bottom Layer w10: JE3.4 250,2750 250,2680 284,2646 1134,2646 1258.54,2521.46 v1(1330,2521.46)
EVAL_I2S2EXT_SD_PB14: JE3.40 R41.2 | length 344.1
  Top Layer w10: R41.2 v1(1870,2600)
  Bottom Layer w10: v1(1870,2600) 1890,2600 1950,2660 1950,2750 JE3.40
EVAL_I2S2EXT_SD_PI2: JE3.2 R31.2 | length 1534.8
  Top Layer w10: v1(1330,2360) R31.2
  Bottom Layer w10: JE3.2 150,2750 150,2670 230,2590 1090,2590 v1(1330,2360)
EVAL_MCO: JE3.17 R50.1 | length 128.4
  Top Layer w10: JE3.17 900,2668.5 R50.1
EVAL_UART5_CTS: JD2.8 R80.2 | length 2683.4
  Top Layer w10: JD2.8 290,2200 360,2130 360,1720 480,1600 v1(1120,1600) ; v1(1120,1370) 1120,640 1180,580 R80.2
  Layer 2 w10: v1(1120,1370) v1(1120,1600)
EVAL_UART5_RTS: JD2.9 R90.2 | length 2963.2
  Top Layer w10: JD2.9 95,2100 47.5,2052.5 47.5,1682.5 80,1650 270,1650 440,1480 v1(1060,1480) ; v1(1060,1300) 1060,430 1120,370 1270,370 R90.2
  Layer 2 w10: v1(1060,1300) v1(1060,1480)
EVAL_UART5_RX: JD2.10 R60.2 | length 2359.9
  Top Layer w10: JD2.10 300,2100 330,2070 330,1710 470,1570 1220,1570 1240,1550 1240,855 1272.5,822.5 R60.2
EVAL_UART5_TX: JD2.7 R70.2 | length 2567.9
  Top Layer w10: JD2.7 150,2150 150,2080 180,2050 270,2050 300,2020 300,1700 460,1540 1150,1540 1180,1510 1180,795 1242.5,732.5 R70.2
EVAL_USART6_CTS: JD2.21 R81.2 | length 2303.8
  Top Layer w10: JD2.21@110,1500 JD2.21 47.5,1447.5 47.5,1380 77.5,1350 1060,1350 1090,1320 1090,580 1150,520 R81.2
EVAL_USART6_RTS: JE3.22 R91.2 | length 3793.7
  Top Layer w10: JE3.22 1130,2800 1180,2750 1230,2750 1250,2730 1250,2660 1270,2640 2010,2640 2040,2610 2040,560 1950,470 1449.8,470 R91.2
EVAL_USART6_RX: JE3.20 R61.2 | length 3432.3
  Top Layer w10: R61.2 v1(1412.78,927.22) ; v1(2010,930) v1(2010,1550)
  Layer 2 w10: JE3.20 1020,2800 1070,2750 1120,2750 1150,2720 1150,2675 1185,2640 1970,2640 2010,2600 v1(2010,1550) ; v1(1412.78,927.22) 2007.22,927.22 v1(2010,930)
EVAL_USART6_TX: JD2.23 R71.2 | length 2059.7
  Top Layer w10: JD2.23 150,1450 1130,1450 1150,1430 1150,740 1217.5,672.5 R71.2
EVAL_VCC: J1.1 JE3.48 | length 2322.7
  Top Layer w20: v2(1670,1450) 1670,1152.97 J1.1
  Layer 2 w20: v2(1670,1450) 2300,1450 2350,1500 2350,2750 JE3.48
GND: C1.1 C2.1 JA1.2 JD1.1 JD1.2 JD1.6 JD1.24 JD2.2 JE3.1 JE3.10 JE3.30 JE3.39 JE3.50 JR1.2 JR1.20 JR2.19 Y1.2
  other v1: 260,200 430,230 680,230 2000,300 950,370 260,450 2300,450 370,520 260,550 950,600 1160,670 260,700 600,700 450,740 1930,770 260,800 950,800 2010,880 2300,900 260,950 330,950 400,950 520,950 680,950 750,1100 950,1100 1500,1100 600,1300 950,1300 1400,1300 1800,1390 250,1420 820,1420 950,1420 1090,1420 350,1500 1330,1540 1560,1540 1860,1540 2280,1550 1940,1680 840,1740 2280,1750 1920,1790 1000,1800 1140,1800 1280,1800 800,2000 2280,2050 1000,2090 1140,2090 1280,2090 1400,2090 1500,2090 800,2170 350,2210 1050,2250 1280,2250 1450,2250 310,2300 460,2340 770,2350 1870,2350 1050,2380 1200,2380 340,2400 980,2430 1950,2440 370,2460 500,2460 600,2460 700,2460 800,2460 900,2460 1100,2490 450,2530 650,2530 850,2530 1280,2580 350,2670 450,2670 550,2670 650,2670 750,2670 850,2670 950,2670 1050,2670 1350,2670 1550,2670 1750,2670
NetJ3_1: J3.1 R60.1 R61.1 | length 296.3
  Top Layer w10: R60.1 1522.5,822.5 1550,850 ; R61.1 1517.5,882.5 1550,850 ; J3.1 1550,850
NetJ4_1: J4.1 R70.1 R71.1 | length 296.3
  Top Layer w10: R71.1 1522.5,672.5 1550,700 ; R70.1 1517.5,732.5 1550,700 ; J4.1 1550,700
NetJ5_1: J5.1 R80.1 R81.1 | length 302.2
  Top Layer w10: R81.1 1520,520 1550,550 ; R80.1 1520,580 1550,550 ; J5.1 1550,550
NetJ6_1: J6.1 R90.1 R91.1 | length 312.2
  Top Layer w10: R90.1@1472.8,360 R90.1@1472.8,365 ; R90.1 1520,370 1550,400 ; R91.1 1520,430 1550,400 ; R91.1@1472.8,440 R91.1@1477.79,440 ; J6.1 1550,400
NetR1_1: R1.1 Y1.3 | length 89.4
  Top Layer w10: R1.1 856.73,2400 Y1.3
NetR2_1: R2.1 Y1.1 | length 85.5
  Top Layer w10: R2.1@959.53,2199.21 R2.1 961.5,2279.49 Y1.1
pads on no net: FID1.1 FID2.1 FID3.1 JA1.4 JA1.6 JA1.7 JA1.9 JA1.10 JD1.3 JD1.4 JD1.5 JD1.7 JD1.8 JD1.9 JD1.10 JD1.11 JD1.12 JD1.13 JD1.14 JD1.16 JD1.17 JD1.18 JD1.19 JD1.20 JD1.21 JD1.22 JD1.23 JD1.25 JD1.26 JD1.27 JD1.28 JD1.29 JD1.30 JD1.32 JD1.33 JD1.34 JD1.35 JD1.36 JD1.37 JD1.38 JD1.40 JD1.41 JD1.45 JD1.46 JD1.47 JD1.48 JD1.49 JD1.50 JD2.3 JD2.4 JD2.6 JD2.11 JD2.13 JD2.14 JD2.15 JD2.16 JD2.17 JD2.18 JD2.20 JD2.22 JD2.27 JD2.30 JD2.31 JD2.34 JD2.35 JD2.37 JD2.39 JD2.40 JD2.41 JD2.42 JD2.43 JD2.44 JD2.46 JD2.48 JD2.49 JD2.50 JE3.5 JE3.6 JE3.7 JE3.8 JE3.9 JE3.11 JE3.12 JE3.13 JE3.14 JE3.15 JE3.16 JE3.18 JE3.19 JE3.23 JE3.24 JE3.25 JE3.26 JE3.27 JE3.28 JE3.29 JE3.31 JE3.32 JE3.33 JE3.34 JE3.35 JE3.36 JE3.37 JE3.43 JE3.44 JE3.45 JE3.46 JE3.47 JE3.49 JR1.1 JR1.3 JR1.4 JR1.5 JR1.6 JR1.7 JR1.8 JR1.9 JR1.10 JR1.11 JR1.13 JR1.15 JR1.17 JR1.19 JR1.MH1 JR1.MH2 JR2.1 JR2.5 JR2.6 JR2.7 JR2.8 JR2.9 JR2.15 JR2.16 JR2.17 JR2.18 JR2.20 JR2.MH1 JR2.MH2 Logo1.0 SH-J1.0 SH-J2.0 SH-J3.0 SH-J4.0 SH-J5.0 SH-J6.0 SH-J7.0 SH-J8.0 SH-J9.0

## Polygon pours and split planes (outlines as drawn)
GND on Top Layer "Top Layer-GND" (solid, remove dead copper, pour order 2): 0,0 2600,0 2600,2900 0,2900
GND on Bottom Layer "Bottom Layer-GND" (solid, remove dead copper, pour order 4): 0,2900 2600,2900 2600,0 0,0
GND on Layer 2 "Layer 2-GND" (solid, remove dead copper, pour order 6): 0,0 2600,0 2600,2900 0,2900
GND on Layer 3 "Layer 3-GND" (solid, remove dead copper, pour order 8): 0,0 2600,0 2600,2900 0,2900

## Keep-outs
Keep-Out Layer:
  lines w10: -5,0 ccw(c0,0) 0,-5 ; -5,0 ccw(c0,0) 0,-5 ; -5,0 -5,2900 ; -5,2900 cw(c0,2900) 0,2905 ; -5,2900 cw(c0,2900) 0,2905 ; 0,-5 2600,-5 ; 0,2905 2600,2905 ; 2600,-5 ccw(c2600,0) 2605,0 ; 2600,-5 ccw(c2600,0) 2605,0 ; 2600,2905 cw(c2600,2900) 2605,2900 ; 2600,2905 cw(c2600,2900) 2605,2900 ; 2605,0 2605,2900
  text ".Layer_Name" at 567,-853.49 h60

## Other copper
Top Layer:
  text "©" at 480,80 h105
  text ".CopyRYr" at 574,80 h60
  text "TI" at 850,80 h60
  text ".Layer_Name" at 567,-853.49 h60
Bottom Layer:
  text "UL94V-0" at 2430,610 h60 r90
  text "MADE IN U.S." at 1593.91,101.11 h60
  text ".Layer_Name" at 567,-853.49 h60

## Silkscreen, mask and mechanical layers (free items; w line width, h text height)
Top Overlay:
  region: 2340,1930 2340,1630 2440,1630 2440,1930
  text "EVAL" at 770,2580 h40
  text "DIN" at 1550,2580 h40
  text "DAC_MCLK" at 610,2510 h40
  text "WS" at 1570,2500 h40
  text "CLK" at 1550,2420 h40
  text "EVAL" at 1210,2370 h40 r90
  text "DOUT" at 1520,2310 h40
  text "PCM/I2S" at 1250,2150 h60
  text "DIN" at 1520,1990 h40
  text "DOUT" at 1520,1890 h40
  text "CLK" at 1520,1820 h40
  text "WS" at 1520,1750 h40
  text "DISCOVERY" at 1210,1730 h40 r90
  text "-" at 2430,1570 h60 r90
  text ".PCB_Rev" at 2430,1340 h60 r90
  text "EVAL" at 1690,1240 h40 r90
  text "CC256xEM" at 1790,1240 h40 r90
  text "DISCOVERY" at 1890,1240 h40 r90
  text "DISCOVERY" at 840,980 h40
  text "AP" at 840,880 h40
  text "EVAL" at 840,780 h40
  text "UART" at 1210,520 h60 r90
  text ".PRJ_Number" at 2430,330 h60 r90
  text "DISCOVERY" at 310,180 h40
  text "DAC_MCLK" at 450,30 h40
  text ".Layer_Name" at 567,-853.49 h60
Bottom Overlay:
  text "FOR EVALUATION ONLY; NOT FCC APPROVED FOR RESALE." at 2340,2430 h50 r90
  text ".Layer_Name" at 567,-853.49 h60
Top Paste:
  text ".Layer_Name" at 567,-853.49 h60
Bottom Paste:
  text ".Layer_Name" at 567,-853.49 h60
Top Solder:
  text ".Layer_Name" at 567,-853.49 h60
  text ".Layer_Name" at 567,-853.49 h60
Bottom Solder:
  text ".Layer_Name" at 567,-853.49 h60
Drill Guide:
  text ".Layer_Name" at 567,-853.49 h60
M1 Board Outline:
  the board outline again, w10
  text ".Layer_Name" at 567,-853.49 h60
M2 Board Dimensions:
  rectangle: 115,-395 490,-270
  rectangle: -10,-270 115,-145
  lines w7: -10,-270 990,-270 ; 115,-395 115,-145 ; 240,-395 240,-145 ; 490,-395 490,-145 ; 740,-395 740,-145 ; -10,-395 -10,-145 990,-145 990,-395 -10,-395
  text ".Layer_Name" at 567,-853.49 h60
M3 3D STEP Top:
  text ".Layer_Name" at 567,-853.49 h60
M4 3D STEP Bottom:
  text ".Layer_Name" at 567,-853.49 h60
M5 Assembly Top:
  lines w10: -302,-925.17 6298,-925.17 ; -302,-721.83 6300,-721.83 ; -302,-518.5 -302,-1128.5 3703,-1128.5 6300,-1128.5 6300,-518.5 -301.5,-518.5 -301.5,-1128.5 1274,-1128.5 ; 2163,-1128.5 2163,-518.5 ; 3430,-721.83 3430,-518.5 ; 4270,-721.83 4270,-518.5 ; 4892,-1135 4892,-932.17
  text "COMPONENTS MARKED 'DNP' SHOULD NOT BE POPULATED." at 1143.5,-313.5 h60
  text "ASSEMBLY VARIANT:" at 1143,-429 h60
  text ".VariantName" at 2179,-429 h60
  text "PCB VIEWED FROM TOP SIDE" at -238.5,-650.67 h60
  text "BOARD #:" at 2238,-650.67 h60
  text ".PRJ_Number" at 2783.5,-650.67 h60
  text "REV:" at 3628,-650.67 h60
  text ".PCB_Rev" at 3919.5,-650.67 h60
  text "SVN REV:" at 4466,-650.67 h60
  text ".VersionControl_RevNumber" at 4972,-650.67 h60
  text "PLOT NAME =" at -238.5,-1059.33 h60
  text ".plot_File_Name" at 567,-1059.33 h60
  text "GENERATED    :" at 2240,-1059.33 h60
  text ".Print_Date" at 3109.5,-1059.33 h60
  text ".Print_Time" at 3838.5,-1059.33 h60
  text "TEXAS INSTRUMENTS" at 5103,-1059.33 h60
M6 Assembly Bottom:
  lines w10: -302.5,-722.33 6299.5,-722.33 ; -300.5,-925.67 6299.5,-925.67 ; 1105.5,-1135.5 1105.5,-932.67 ; 1727.5,-722.33 1727.5,-519 ; 2567.5,-722.33 2567.5,-519 ; 3834.5,-1129 3834.5,-519 ; 4723.5,-1129 6299,-1129 6299,-519 -302.5,-519 -302.5,-1129 2294.5,-1129 6299.5,-1129 6299.5,-519
  text "COMPONENTS MARKED 'DNP' SHOULD NOT BE POPULATED." at 6092,-313 h60
  text ".VariantName" at 5048,-429 h60
  text "ASSEMBLY VARIANT:" at 6087,-429 h60
  text ".VersionControl_RevNumber" at 1025.5,-651.17 h60
  text "SVN REV:" at 1531.5,-651.17 h60
  text ".PCB_Rev" at 2078,-651.17 h60
  text "REV:" at 2369.5,-651.17 h60
  text ".PRJ_Number" at 3214,-651.17 h60
  text "BOARD #:" at 3759.5,-651.17 h60
  text "PCB VIEWED FROM BOTTOM SIDE" at 6236,-651.17 h60
  text "TEXAS INSTRUMENTS" at 894.5,-1059.83 h60
  text ".Print_Time" at 2159,-1059.83 h60
  text ".Print_Date" at 2888,-1059.83 h60
  text "GENERATED    :" at 3757.5,-1059.83 h60
  text ".plot_File_Name" at 5430.5,-1059.83 h60
  text "PLOT NAME =" at 6236,-1059.83 h60
M9 Title Sheet:
  drawing of 57 lines, arcs and shapes, not listed
  text "1" at 729.84,8041.5 h70
  text "2" at 3225.5,8041.5 h70
  text "3" at 5714.84,8041.5 h70
  text "4" at 8221.51,8041.5 h70
  text "5" at 10720.5,8041.5 h70
  text "6" at 13225.5,8041.5 h70
  text "A" at -426.5,6898.5 h70
  text "A" at 14373.5,6898.5 h70
  text "B" at -426.5,4518.5 h70
  text "B" at 14373.5,4518.5 h70
  text "C" at -426.5,2143.5 h70
  text "C" at 14373.5,2143.5 h70
  text "PROJECT TITLE:" at 11333.5,282.5 h45
  text ".PRJ_Title" at 11383.5,149.17 h70
  text "DESIGNED FOR:" at 11333.5,-18.5 h45
  text ".PRJ_Customer" at 11383.5,-158.5 h70
  text "D" at -426.5,-226.5 h70
  text "D" at 14373.5,-226.5 h70
  text "FILE NAME:" at 11333.5,-318.5 h45
  text ".PCB_File_Name_No_Path" at 11383.5,-438.5 h70
  text "Texas Instruments (TI) and/or its licensors do not warrant the accuracy or completeness of this specification" at 6364,-600.34 h45
  text "ENGINEER:" at 11333.5,-608.5 h45
  text "LAYOUT BY:" at 12838.5,-608.5 h45
  text "or any information contained therein. TI and/or its licensors do not warrant that this design will meet" at 6319.01,-713 h45
  text ".PRJ_Engineer" at 11383.5,-763.49 h70
  text ".PCB_Layout" at 12889,-763.49 h70
  text "the specifications, will be suitable for your application or fit for any particular purpose, or will operate in" at 6319.01,-825.67 h45
  text ".Layer_Name" at 567,-853.49 h60
  text "ALTIUM DESIGNER VERSION:" at 12838.5,-918.5 h45
  text "an implementation. TI and/or its licensors do not warrant that the design is production worthy. You should" at 6319.01,-938.33 h45
  text "completely validate and test your design implementation to confirm the system functionality for your application." at 6364,-1051 h45
  text ".print_Scale" at 11383.5,-1051.83 h70
  text ".Application_BuildNumber" at 12889,-1051.83 h70
  text "1" at 729.84,-1258.5 h70
  text "2" at 3225.5,-1258.5 h70
  text "3" at 5714.84,-1258.5 h70
  text "4" at 8221.51,-1258.5 h70
  text "5" at 10720.5,-1258.5 h70
  text "6" at 13225.5,-1258.5 h70
M10 Fab Notes:
  drawing of 185 lines, arcs and shapes, not listed
  text "DESIGN INFORMATION" at 12371.02,5915 h60
  text "MIN. TRACK WIDTH:" at 11726.46,5735 h60
  text "10" at 12822.7,5735 h60
  text "MIL" at 12977.46,5735 h60
  text "MIN. CLEARANCE:" at 11726.46,5603 h60
  text "0.2" at 12762.7,5603 h60
  text "mm" at 12977.46,5603 h60
  text "MIN. VIA PAD SIZE:" at 11726.46,5471 h60
  text "22" at 12792.71,5471 h60
  text "MIL" at 12977.46,5471 h60
  text "0.15mm (6MIL)" at 12421.46,5329.29 h60
  text "MINIMUM ANNULAR RING" at 11397.23,5325.01 h60
  text "EXTERNAL" at 13129.46,5325.01 h60
  text "PER" at 11597.23,5207 h60
  text "IPC-D-275 CLASS 2 LEVEL C" at 11817.23,5207 h60
  text "MIL, HOLES" at 13305.46,5094.71 h60
  text "+/-" at 12913,5094 h60
  text "+/-" at 13767,5094 h60
  text "REGISTRATION TOLERANCES:" at 11397.23,5089 h60
  text "METAL" at 12597,5089 h60
  text "5" at 13173.2,5089 h60
  text "3" at 14006.2,5089 h60
  text "MIL" at 14122.46,5089 h60
  text "MATERIAL:" at 11322.46,4879.54 h60
  text "FR-4 High Tg" at 12308.9,4739.21 h60
  text "FR-408" at 11743.46,4730.64 h60
  text "X" at 12155.46,4730.64 h60
  text "OTHER" at 13231.46,4730.64 h60
  text "62 MIL (1.6mm) +/-10%" at 12063.56,4567.92 h60
  text "THICKNESS:" at 11397.23,4563.64 h60
  text "X" at 11935.4,4563.64 h60
  text "OTHER" at 13348.46,4563.64 h60
  text "TOLERANCE:" at 11397.23,4405.64 h60
  text "X" at 12236.53,4405.64 h60
  text "ANSI IPC-6012 TYPE 3 CLASS 2" at 12423.48,4405.64 h60
  text "OTHER +/-" at 12423.46,4249.64 h60
  text "BOW & TWIST:" at 11397.23,4092.64 h60
  text "X" at 12236.53,4092.64 h60
  text "ANSI IPC-6012 TYPE 3 CLASS 2" at 12423.48,4092.64 h60
  text "OTHER +/-" at 12423.46,3934.13 h60
  text "DRILLING:" at 11322.46,3795.64 h60
  text "REFERENCE:" at 11397.23,3678.64 h60
  text "X" at 12045.46,3678.64 h60
  text "AS SHOWN" at 12232.46,3678.64 h60
  text "X" at 12946.46,3678.64 h60
  text "NC_DRILL FILES" at 13083.46,3678.64 h60
  text "PTH MIN COPPER THICKNESS:" at 11397.23,3520.64 h60
  text "X" at 12747.46,3520.64 h60
  text "1MIL" at 12884.46,3520.64 h60
  text "OTHER" at 13381.46,3520.64 h60
  text "BOARD FINISH:" at 11322.46,3361.64 h60
  text "SILKSCREEN:" at 11477.68,3243.64 h60
  text "X" at 12426.46,3243.64 h60
  text "TOP" at 12552.46,3243.64 h60
  text "X" at 12936.46,3243.64 h60
  text "BOTTOM" at 13063.46,3243.64 h60
  text "SILKSCREEN COLOR:" at 11477.68,3076.64 h60
  text "X" at 12425.42,3076.64 h60
  text "WHITE" at 12552.46,3076.64 h60
  text "OTHER" at 13063.46,3076.64 h60
  text "SOLDER RESIST COLOR:" at 11477.68,2906.64 h60
  text "X" at 12045.42,2747.44 h60
  text "GREEN" at 12172.46,2747.44 h60
  text "BLUE" at 12763.46,2747.44 h60
  text "OTHER" at 13301.46,2747.44 h60
  text "IMMERSION GOLD (ENIG)" at 12383.46,2558.92 h60
  text "ENEPIG" at 13721,2555.64 h60
  text "SURFACE FINISH:" at 11322.46,2554.64 h60
  text "X" at 12196.51,2554.64 h60
  text "IMM. TIN/SILVER OR EQUIV" at 11652,2397.64 h60
  text "OTHER" at 13083.46,2397.64 h60
  text "ARRAY/PANEL:" at 11322.46,2218.64 h60
  text "CUT AND TRIM PER MECH LAYER 1" at 12383.46,2214.35 h60
  text "N.C. ROUTE" at 12383.46,2062.64 h60
  text "X" at 13062.46,2062.64 h60
  text "V. SCORE" at 13249.46,2062.64 h60
  text "CERTIFICATION:" at 11322.46,1925.64 h60
  text "MATERIALS AND WORKMANSHIP FOR ALL PCBS" at 12047.46,1925.64 h60
  text "TO MEET OR EXCEED THE REQUIREMENTS OF:" at 12047.46,1827.64 h60
  text "X" at 11673.96,1691.14 h60
  text "ANSI IPC-A-600F CLASS ->" at 11812.96,1691.14 h60
  text "X" at 13452.02,1691.14 h60
  text "2" at 13570.96,1691.14 h60
  text "1" at 13255.96,1689.64 h60
  text "3" at 13924.96,1689.64 h60
  text "X" at 11676.02,1531.64 h60
  text "UL 94V-0" at 11812.96,1531.64 h60
  text "X" at 12488.02,1531.64 h60
  text "RoHS" at 12624.96,1531.64 h60
  text "OTHER" at 13269.36,1531.64 h60
  text "PER ORDER" at 13666.42,1531.64 h60
  text "ADDITIONAL REQUIREMENTS:" at 11322.46,1390.64 h60
  text "MICROSECTION:" at 11397.23,1275.64 h60
  text "YES" at 12302.96,1275.64 h60
  text "REQUIRED" at 13164.46,1119.5 h60
  text "BARE BOARD ELEC. TEST:" at 11397.23,1116.64 h60
  text "NONE" at 12702.96,1116.64 h60
  text "X" at 13037.46,1116.64 h60
  text "PER ORDER" at 13756.46,1116.64 h60
  text "MANUFACTURER'S UL:" at 11397.23,959.64 h60
  text "RAIL" at 12562.96,955.35 h60
  text "METAL" at 13054.77,955.35 h60
  text "X" at 13430,955 h60
  text "SILK" at 13566.46,955.35 h60
  text ".Layer_Name" at 567,-853.49 h60
M11 Gerber Information:
  lines w10: -302,-925.17 6298,-925.17 ; -302,-721.83 6300,-721.83 ; -302,-518.5 -302,-1128.5 3703,-1128.5 6300,-1128.5 6300,-518.5 -301.5,-518.5 -301.5,-1128.5 1274,-1128.5 ; 2163,-1128.5 2163,-518.5 ; 3430,-721.83 3430,-518.5 ; 4270,-721.83 4270,-518.5 ; 4892,-1135 4892,-932.17
  text "ALL ARTWORK VIEWED FROM TOP SIDE" at -238.5,-650.67 h60
  text "BOARD #:" at 2238,-650.67 h60
  text ".PRJ_Number" at 2783.5,-650.67 h60
  text "REV:" at 3628,-650.67 h60
  text ".PCB_Rev" at 3919.5,-650.67 h60
  text "SVN REV:" at 4466,-650.67 h60
  text ".VersionControl_RevNumber" at 4972,-650.67 h60
  text "LAYER NAME =" at -238.5,-853.49 h60
  text "PLOT NAME =" at -238.5,-1059.33 h60
  text ".plot_File_Name" at 567,-1059.33 h60
  text "GENERATED    :" at 2240,-1059.33 h60
  text ".Print_Date" at 3109.5,-1059.33 h60
  text ".Print_Time" at 3838.5,-1059.33 h60
  text "TEXAS INSTRUMENTS" at 5103,-1059.33 h60
M12 Stackup:
  drawing of 295 lines, arcs and shapes, not listed
  text "Layer" at 9800.58,7860 h60
  text "Name" at 10210.49,7860 h60
  text "Material" at 11140.23,7860 h60
  text "Thickness" at 12000,7860 h60
  text "Constant" at 12649.84,7860 h60
  text "Board Layer Stack" at 13219.7,7860 h60
  text "1" at 9800.58,7740 h60
  text "Top Overlay" at 10210.49,7740 h60
  text "2" at 9800.58,7620 h60
  text "Top Solder" at 10210.49,7620 h60
  text "Solder Resist" at 11140.23,7620 h60
  text "0.40mil" at 12000,7620 h60
  text "3.5" at 12649.84,7620 h60
  text "3" at 9800.58,7500 h60
  text "Top Layer" at 10210.49,7500 h60
  text "Copper" at 11140.23,7500 h60
  text "1.40mil" at 12000,7500 h60
  text "4" at 9800.58,7380 h60
  text "Dielectric 1" at 10210.49,7380 h60
  text "FR-4" at 11140.23,7380 h60
  text "10.00mil" at 12000,7380 h60
  text "4.8" at 12649.84,7380 h60
  text "5" at 9800.58,7260 h60
  text "Layer 2" at 10210.49,7260 h60
  text "Copper" at 11140.23,7260 h60
  text "1.40mil" at 12000,7260 h60
  text "6" at 9800.58,7140 h60
  text "Dielectric 2" at 10210.49,7140 h60
  text "FR-4" at 11140.23,7140 h60
  text "36.40mil" at 12000,7140 h60
  text "4.8" at 12649.84,7140 h60
  text "7" at 9800.58,7020 h60
  text "Layer 3" at 10210.49,7020 h60
  text "Copper" at 11140.23,7020 h60
  text "1.40mil" at 12000,7020 h60
  text "8" at 9800.58,6900 h60
  text "Dielectric 3" at 10210.49,6900 h60
  text "FR-4" at 11140.23,6900 h60
  text "10.00mil" at 12000,6900 h60
  text "4.8" at 12649.84,6900 h60
  text "9" at 9800.58,6780 h60
  text "Bottom Layer" at 10210.49,6780 h60
  text "Copper" at 11140.23,6780 h60
  text "1.40mil" at 12000,6780 h60
  text "10" at 9800.58,6660 h60
  text "Bottom Solder" at 10210.49,6660 h60
  text "Solder Resist" at 11140.23,6660 h60
  text "0.40mil" at 12000,6660 h60
  text "3.5" at 12649.84,6660 h60
  text "11" at 9800.58,6540 h60
  text "Bottom Overlay" at 10210.49,6540 h60
  text ".Layer_Name" at 567,-853.49 h60
M13 Component Bodies Top:
  text ".Layer_Name" at 567,-853.49 h60
M14 Component Bodies Bottom:
  text ".Layer_Name" at 567,-853.49 h60
M15 Courtyards Top:
  text ".Layer_Name" at 567,-853.49 h60
M16 Courtyards Bottom:
  text ".Layer_Name" at 567,-853.49 h60
Drill Drawing:
  circle w1: c2942.72,2392.4 r24.89
  lines w1: 2917.83,2230.64 2930.27,2230.64 2942.72,2218.2 2955.16,2230.64 2967.6,2230.64 2955.16,2243.08 2967.6,2255.53 2955.16,2255.53 2942.72,2267.97 2930.27,2255.53 2917.83,2255.53 2930.27,2243.08 2917.83,2230.64 ; 2917.83,2529.28 2930.27,2529.28 2930.27,2516.84 2955.16,2516.84 2955.16,2529.28 2967.6,2529.28 2967.6,2554.17 2955.16,2554.17 2955.16,2566.61 2930.27,2566.61 2930.27,2554.17 2917.83,2554.17 2917.83,2529.28 ; 2917.83,2666.16 2967.6,2666.16 2967.6,2715.93 2917.83,2715.93 2917.83,2666.16
  lines w12: 2850,2173.4 4968.02,2173.4 ; 2850,2770.68 4968.02,2770.68 ; 3220.36,2024.08 3220.36,2920 ; 3577.36,2024.08 3577.36,2920 ; 4238.93,2024.08 4238.93,2920 ; 4523.07,2024.08 4523.07,2920 ; 2850,2024.08 4968.02,2024.08 4968.02,2920 2850,2920 2850,2024.08
  text "Symbol" at 2939.59,2815.48 h72
  text "Quantity" at 3265.16,2815.48 h72
  text "Finished Hole Size" at 3622.16,2815.48 h72
  text "Plated" at 4283.72,2815.48 h72
  text "Hole Type" at 4567.86,2815.48 h72
  text "4" at 3265.16,2666.16 h60
  text "57.09mil (1.450mm)" at 3622.16,2666.16 h60
  text "NPTH" at 4283.72,2666.16 h60
  text "Round" at 4567.86,2666.16 h60
  text "134" at 3265.16,2516.84 h60
  text "10.00mil (0.254mm)" at 3622.16,2516.84 h60
  text "PTH" at 4283.72,2516.84 h60
  text "Round" at 4567.86,2516.84 h60
  text "27" at 3265.16,2367.52 h60
  text "39.37mil (1.000mm)" at 3622.16,2367.52 h60
  text "PTH" at 4283.72,2367.52 h60
  text "Round" at 4567.86,2367.52 h60
  text "150" at 3265.16,2218.2 h60
  text "40.94mil (1.040mm)" at 3622.16,2218.2 h60
  text "PTH" at 4283.72,2218.2 h60
  text "Round" at 4567.86,2218.2 h60
  text "315 Total" at 3265.16,2068.88 h60
  text ".Layer_Name" at 567,-853.49 h60

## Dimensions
-10,5 to 2600,0 on M2 Board Dimensions
-10,5 to 0,2900 on M2 Board Dimensions
-10,-395 to 990,-395 on M2 Board Dimensions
